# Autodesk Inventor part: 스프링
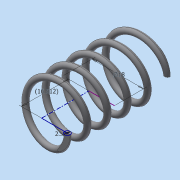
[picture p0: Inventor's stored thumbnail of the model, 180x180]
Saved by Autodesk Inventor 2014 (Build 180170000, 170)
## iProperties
Created: 2024-02
Part Number: 스프링
Material: 스테인레스 스틸
Document SubType Name: Modeling
Designer: dg
Density: 8.08 g/cm^3
Appearance: 반연마
Mass: 0.87168 g
Surface Area: 17.7171 cm^2
Volume: 0.87168 cm^3
Author: dg
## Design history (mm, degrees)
sketch "스케치1"
  geometry: L1 (0, 0)-(9, 0); L2 (0, 0)-(0, 28.5); L3 (0, 28.5)-(9, 28.5); C1 r 1 at (9, 0)
  constraints: 6 end point, 2 perpendicular, 1 centre point, 1 coincident, 1 horizontal, 1 parallel
  dimensions: "d0" = 28.5 distance of L1.start L2.end (derived); "d1" = 18 diameter of L3.end L2; "d2" = 2 diameter of C1
feature "코일1" pitch "d4" = 10; turns "d6" = 5; dims "d5" = 28.5 (= d0), "d7" = 0, angle "d8" = 90 deg, angle "d9" = 90 deg, "d10" = 0, "d11" = 0
node "작업 평면1"
feature "분할1"
feature "분할2"
node "솔리드1"
